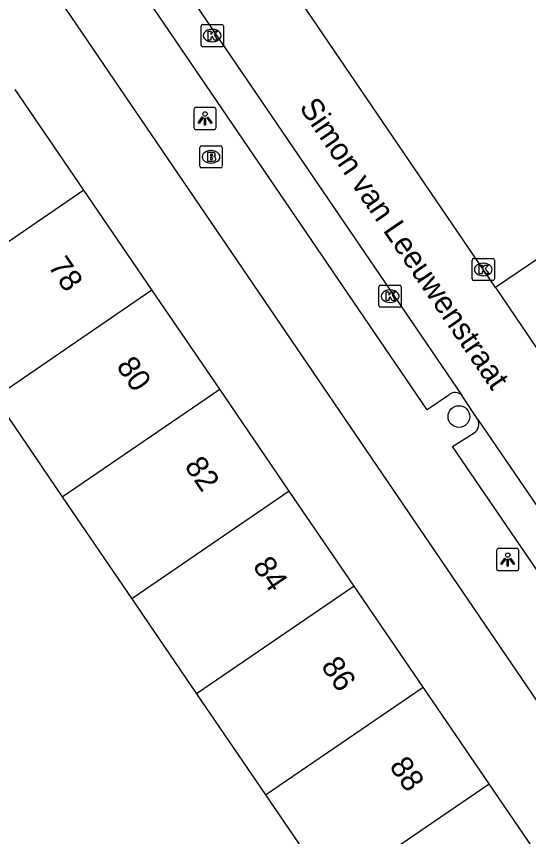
# Model space of a CAD drawing. Extents: x 157466 to 158888, y 383063 to 384677.
# Drawn here: x 158173 to 158196.03, y 383626.43 to 383663.31 of the extents above; entities that cross this region are included whole.
import ezdxf

# ---------------------------------------------------------------- set-up
doc = ezdxf.new("R2010")
doc.units = 0
for name, color, linetype in [('IMGEO_Boom', 7, 'Continuous'), ('IMGEO_Brandkraan', 7, 'Continuous'), ('IMGEO_Kolk', 7, 'Continuous'), ('IMGEO_Lichtpunt', 7, 'Continuous'), ('IMGEO_Openbare_ruimte_label', 7, 'Continuous'), ('IMGEO_Pand', 7, 'Continuous'), ('IMGEO_Pand_nummerreeks', 7, 'Continuous'), ('IMGEO_Rijbaan_lokaal_open', 7, 'Continuous'), ('IMGEO_Voetpad_open', 7, 'Continuous')]:
    doc.layers.add(name, color=color, linetype=linetype)

msp = doc.modelspace()

# ---------------------------------------------------------------- linework, layer by layer
at = {"layer": 'IMGEO_Boom'}
msp.add_circle((158192.902, 383645.313), 0.489, dxfattribs=at)
at = {"layer": 'IMGEO_Brandkraan'}
for p, q in [((158181.255, 383656.567), (158181.255, 383657.419)), ((158181.33, 383657.493), (158182.182, 383657.493)), ((158181.743, 383657.273), (158181.768, 383657.273)), ((158182.256, 383657.419), (158182.256, 383656.567)), ((158181.766, 383656.713), (158181.741, 383656.713)), ((158182.182, 383656.493), (158181.33, 383656.493))]:
    msp.add_line(p, q, dxfattribs=at)
for points in [[(158181.255, 383656.567), (158181.255, 383657.419)], [(158181.33, 383657.493), (158182.182, 383657.493)], [(158182.256, 383657.419), (158182.256, 383656.567)], [(158181.603, 383657.193), (158181.603, 383656.793), (158181.816, 383656.793)], [(158181.834, 383657.193), (158181.603, 383657.193)], [(158181.782, 383657.112), (158181.728, 383657.112), (158181.728, 383657.036)], [(158181.728, 383657.036), (158181.781, 383657.036)], [(158181.79, 383656.96), (158181.728, 383656.96), (158181.728, 383656.879)], [(158181.728, 383656.879), (158181.79, 383656.879)], [(158182.182, 383656.493), (158181.33, 383656.493)]]:
    msp.add_lwpolyline(points, dxfattribs=at)
for centre, radius, start, end in [((158181.332, 383657.417), 0.0765, 91.552, 178.448), ((158181.332, 383657.417), 0.0765, 91.552, 178.448), ((158182.18, 383657.417), 0.0765, 1.552, 88.448), ((158182.18, 383657.417), 0.0765, 1.552, 88.448), ((158181.783, 383657.074), 0.0379, 267.8285, 90.9355), ((158181.791, 383656.919), 0.0404, 269.8759, 90.5077), ((158181.838, 383657.048), 0.145, 59.4692, 91.5367), ((158181.863, 383657.095), 0.0922, 285.5137, 58.1501), ((158181.868, 383656.903), 0.105, 301.3115, 78.989), ((158181.332, 383656.569), 0.0765, 181.552, 268.448), ((158181.332, 383656.569), 0.0765, 181.552, 268.448), ((158181.822, 383657.044), 0.251, 268.6676, 293.5347), ((158182.18, 383656.569), 0.0765, 271.552, 358.448), ((158182.18, 383656.569), 0.0765, 271.552, 358.448)]:
    msp.add_arc(centre, radius, start, end, dxfattribs=at)
for centre, major_axis, ratio, start_param, end_param in [((158181.742, 383656.993), (-0.387, 0.002), 0.722429, 4.712389, 7.853982), ((158181.767, 383656.993), (-0.39, 0.002), 0.717154, 1.570796, 4.712389)]:
    msp.add_ellipse(centre, major_axis=major_axis, ratio=ratio, start_param=start_param, end_param=end_param, dxfattribs=at)
at = {"layer": 'IMGEO_Kolk'}
for p, q in [((158181.307, 383662.021), (158181.307, 383662.873)), ((158181.382, 383662.947), (158182.234, 383662.947)), ((158182.308, 383662.873), (158182.308, 383662.021)), ((158181.795, 383662.727), (158181.82, 383662.727)), ((158181.818, 383662.167), (158181.793, 383662.167)), ((158182.234, 383661.947), (158181.382, 383661.947)), ((158193.495, 383651.502), (158193.495, 383652.354)), ((158193.57, 383652.428), (158194.422, 383652.428)), ((158193.983, 383652.208), (158194.008, 383652.208)), ((158194.496, 383652.354), (158194.496, 383651.502)), ((158194.422, 383651.428), (158193.57, 383651.428)), ((158194.006, 383651.648), (158193.981, 383651.648)), ((158189.305, 383650.303), (158189.305, 383651.155)), ((158189.38, 383651.229), (158190.232, 383651.229)), ((158189.793, 383651.009), (158189.818, 383651.009)), ((158190.306, 383651.155), (158190.306, 383650.303)), ((158189.816, 383650.449), (158189.791, 383650.449)), ((158190.232, 383650.229), (158189.38, 383650.229))]:
    msp.add_line(p, q, dxfattribs=at)
for points in [[(158181.307, 383662.021), (158181.307, 383662.873)], [(158181.382, 383662.947), (158182.234, 383662.947)], [(158182.308, 383662.873), (158182.308, 383662.021)], [(158181.628, 383662.647), (158181.751, 383662.647), (158181.751, 383662.496), (158181.881, 383662.647), (158182.045, 383662.647), (158181.899, 383662.496), (158182.052, 383662.247), (158181.9, 383662.247), (158181.815, 383662.411), (158181.751, 383662.344), (158181.751, 383662.247), (158181.628, 383662.247), (158181.628, 383662.647)], [(158182.234, 383661.947), (158181.382, 383661.947)], [(158193.495, 383651.502), (158193.495, 383652.354)], [(158193.57, 383652.428), (158194.422, 383652.428)], [(158193.816, 383652.128), (158193.939, 383652.128), (158193.939, 383651.977), (158194.069, 383652.128), (158194.233, 383652.128), (158194.087, 383651.977), (158194.24, 383651.728), (158194.088, 383651.728), (158194.003, 383651.892), (158193.939, 383651.825), (158193.939, 383651.728), (158193.816, 383651.728), (158193.816, 383652.128)], [(158194.496, 383652.354), (158194.496, 383651.502)], [(158194.422, 383651.428), (158193.57, 383651.428)], [(158189.305, 383650.303), (158189.305, 383651.155)], [(158189.38, 383651.229), (158190.232, 383651.229)], [(158190.306, 383651.155), (158190.306, 383650.303)], [(158189.626, 383650.929), (158189.749, 383650.929), (158189.749, 383650.778), (158189.879, 383650.929), (158190.043, 383650.929), (158189.897, 383650.778), (158190.05, 383650.529), (158189.898, 383650.529), (158189.813, 383650.693), (158189.749, 383650.626), (158189.749, 383650.529), (158189.626, 383650.529), (158189.626, 383650.929)], [(158190.232, 383650.229), (158189.38, 383650.229)]]:
    msp.add_lwpolyline(points, dxfattribs=at)
for centre, start, end in [((158181.384, 383662.871), 91.552, 178.448), ((158181.384, 383662.871), 91.552, 178.448), ((158182.232, 383662.871), 1.552, 88.448), ((158182.232, 383662.871), 1.552, 88.448), ((158181.384, 383662.023), 181.552, 268.448), ((158181.384, 383662.023), 181.552, 268.448), ((158182.232, 383662.023), 271.552, 358.448), ((158182.232, 383662.023), 271.552, 358.448), ((158193.572, 383652.352), 91.552, 178.448), ((158193.572, 383652.352), 91.552, 178.448), ((158194.42, 383652.352), 1.552, 88.448), ((158194.42, 383652.352), 1.552, 88.448), ((158193.572, 383651.504), 181.552, 268.448), ((158193.572, 383651.504), 181.552, 268.448), ((158194.42, 383651.504), 271.552, 358.448), ((158194.42, 383651.504), 271.552, 358.448), ((158189.382, 383651.153), 91.552, 178.448), ((158189.382, 383651.153), 91.552, 178.448), ((158190.23, 383651.153), 1.552, 88.448), ((158190.23, 383651.153), 1.552, 88.448), ((158189.382, 383650.305), 181.552, 268.448), ((158189.382, 383650.305), 181.552, 268.448), ((158190.23, 383650.305), 271.552, 358.448), ((158190.23, 383650.305), 271.552, 358.448)]:
    msp.add_arc(centre, 0.0765, start, end, dxfattribs=at)
for centre, major_axis, ratio, start_param, end_param in [((158181.794, 383662.447), (-0.387, 0.002), 0.722429, 4.712389, 7.853982), ((158181.819, 383662.447), (-0.39, 0.002), 0.717154, 1.570796, 4.712389), ((158193.982, 383651.928), (-0.387, 0.002), 0.722429, 4.712389, 7.853982), ((158194.007, 383651.928), (-0.39, 0.002), 0.717154, 1.570796, 4.712389), ((158189.792, 383650.729), (-0.387, 0.002), 0.722429, 4.712389, 7.853982), ((158189.817, 383650.729), (-0.39, 0.002), 0.717154, 1.570796, 4.712389)]:
    msp.add_ellipse(centre, major_axis=major_axis, ratio=ratio, start_param=start_param, end_param=end_param, dxfattribs=at)
at = {"layer": 'IMGEO_Lichtpunt'}
for p, q in [((158180.989, 383659.122), (158180.989, 383658.315)), ((158180.989, 383659.122), (158180.989, 383658.315)), ((158181.891, 383659.217), (158181.083, 383659.217)), ((158181.891, 383659.217), (158181.083, 383659.217)), ((158181.985, 383658.315), (158181.985, 383659.122)), ((158181.985, 383658.315), (158181.985, 383659.122)), ((158181.083, 383658.221), (158181.891, 383658.221)), ((158181.083, 383658.221), (158181.891, 383658.221)), ((158194.595, 383639.289), (158194.595, 383638.482)), ((158194.595, 383639.289), (158194.595, 383638.482)), ((158195.497, 383639.384), (158194.689, 383639.384)), ((158195.497, 383639.384), (158194.689, 383639.384)), ((158195.591, 383638.482), (158195.591, 383639.289)), ((158195.591, 383638.482), (158195.591, 383639.289)), ((158194.689, 383638.388), (158195.497, 383638.388)), ((158194.689, 383638.388), (158195.497, 383638.388))]:
    msp.add_line(p, q, dxfattribs=at)
for points in [[(158181.363, 383658.786), (158181.402, 383658.758), (158181.214, 383658.496), (158181.176, 383658.523), (158181.363, 383658.786)], [(158181.575, 383658.758), (158181.613, 383658.785), (158181.8, 383658.523), (158181.761, 383658.495), (158181.575, 383658.758)], [(158181.465, 383658.738), (158181.512, 383658.738), (158181.512, 383658.416), (158181.465, 383658.416), (158181.465, 383658.738)], [(158194.969, 383638.953), (158195.008, 383638.925), (158194.82, 383638.663), (158194.782, 383638.69), (158194.969, 383638.953)], [(158195.071, 383638.905), (158195.118, 383638.905), (158195.118, 383638.583), (158195.071, 383638.583), (158195.071, 383638.905)], [(158195.181, 383638.925), (158195.219, 383638.952), (158195.406, 383638.69), (158195.367, 383638.662), (158195.181, 383638.925)]]:
    msp.add_lwpolyline(points, dxfattribs=at)
for centre in [(158181.488, 383658.92), (158195.094, 383639.087)]:
    msp.add_circle(centre, 0.0994, dxfattribs=at)
for centre, start, end in [((158181.083, 383659.122), 90, 180), ((158181.083, 383659.122), 90, 180), ((158181.891, 383659.122), 0, 90), ((158181.891, 383659.122), 0, 90), ((158181.083, 383658.315), 180, 270), ((158181.083, 383658.315), 180, 270), ((158181.891, 383658.315), 270, 0), ((158181.891, 383658.315), 270, 360), ((158194.689, 383639.289), 90, 180), ((158194.689, 383639.289), 90, 180), ((158195.497, 383639.289), 0, 90), ((158195.497, 383639.289), 0, 90), ((158194.689, 383638.482), 180, 270), ((158194.689, 383638.482), 180, 270), ((158195.497, 383638.482), 270, 0), ((158195.497, 383638.482), 270, 360)]:
    msp.add_arc(centre, 0.0946, start, end, dxfattribs=at)
at = {"layer": 'IMGEO_Pand'}
for points in [[(158176.039, 383655.489), (158172.949, 383660.017)], [(158176.039, 383655.489), (158168.956, 383650.65)], [(158179.097, 383651.01), (158176.039, 383655.489)], [(158172.013, 383646.171), (158179.097, 383651.01)], [(158182.145, 383646.544), (158179.097, 383651.01)], [(158175.062, 383641.704), (158182.145, 383646.544)], [(158185.272, 383641.963), (158182.145, 383646.544)], [(158172.013, 383646.171), (158175.062, 383641.704)], [(158185.272, 383641.963), (158178.188, 383637.124)], [(158188.192, 383637.685), (158185.272, 383641.963)], [(158175.062, 383641.704), (158178.188, 383637.124)], [(158188.192, 383637.685), (158181.108, 383632.845)], [(158191.286, 383633.152), (158188.192, 383637.685)], [(158178.188, 383637.124), (158181.108, 383632.845)], [(158184.202, 383628.312), (158191.286, 383633.152)], [(158194.254, 383628.803), (158191.286, 383633.152)], [(158181.108, 383632.845), (158184.202, 383628.312)], [(158187.171, 383623.963), (158194.254, 383628.803)], [(158197.343, 383624.278), (158194.254, 383628.803)], [(158184.202, 383628.312), (158187.171, 383623.963)]]:
    msp.add_lwpolyline(points, dxfattribs=at)
at = {"layer": 'IMGEO_Rijbaan_lokaal_open'}
for points in [[(158194.546, 383651.117), (158182.697, 383668.557)], [(158180.345, 383664.898), (158193.044, 383646.255)], [(158194.546, 383651.117), (158196.976, 383647.54), (158197.105, 383647.46)], [(158193.758, 383645.189), (158193.044, 383646.255)], [(158193.758, 383645.189), (158206.716, 383626.203)]]:
    msp.add_lwpolyline(points, dxfattribs=at)
at = {"layer": 'IMGEO_Voetpad_open'}
for points in [[(158190.562, 383676.72), (158203.531, 383657.208), (158194.546, 383651.117)], [(158173.059, 383666.844), (158205.841, 383618.66), (158208.263, 383615.093), (158207.826, 383613.566)], [(158192.448, 383646.284), (158191.477, 383645.613), (158179.176, 383663.661), (158180.137, 383664.316)], [(158206.166, 383626.216), (158205.203, 383625.556), (158192.606, 383643.965), (158193.592, 383644.589)]]:
    msp.add_lwpolyline(points, dxfattribs=at)
for centre, radius, start, end in [((158192.732, 383645.982), 0.415, 41.2146, 133.214), ((158193.329, 383644.985), 0.475, 303.5893, 25.4807)]:
    msp.add_arc(centre, radius, start, end, dxfattribs=at)

# ---------------------------------------------------------------- texts
at = {"layer": 'IMGEO_Openbare_ruimte_label'}
msp.add_text('Simon van Leeuwenstraat', height=1, rotation=304.2783, dxfattribs=at).set_placement((158185.691, 383659.22))
at = {"layer": 'IMGEO_Pand_nummerreeks'}
for s, p in [('78', (158174.396, 383652.079)), ('80', (158177.465, 383647.582)), ('82', (158180.532, 383643.09)), ('84', (158183.602, 383638.591)), ('86', (158186.671, 383634.094)), ('88', (158189.743, 383629.595))]:
    msp.add_text(s, height=1, rotation=304.3155, dxfattribs=at).set_placement(p)

doc.saveas('drawing.dxf')
